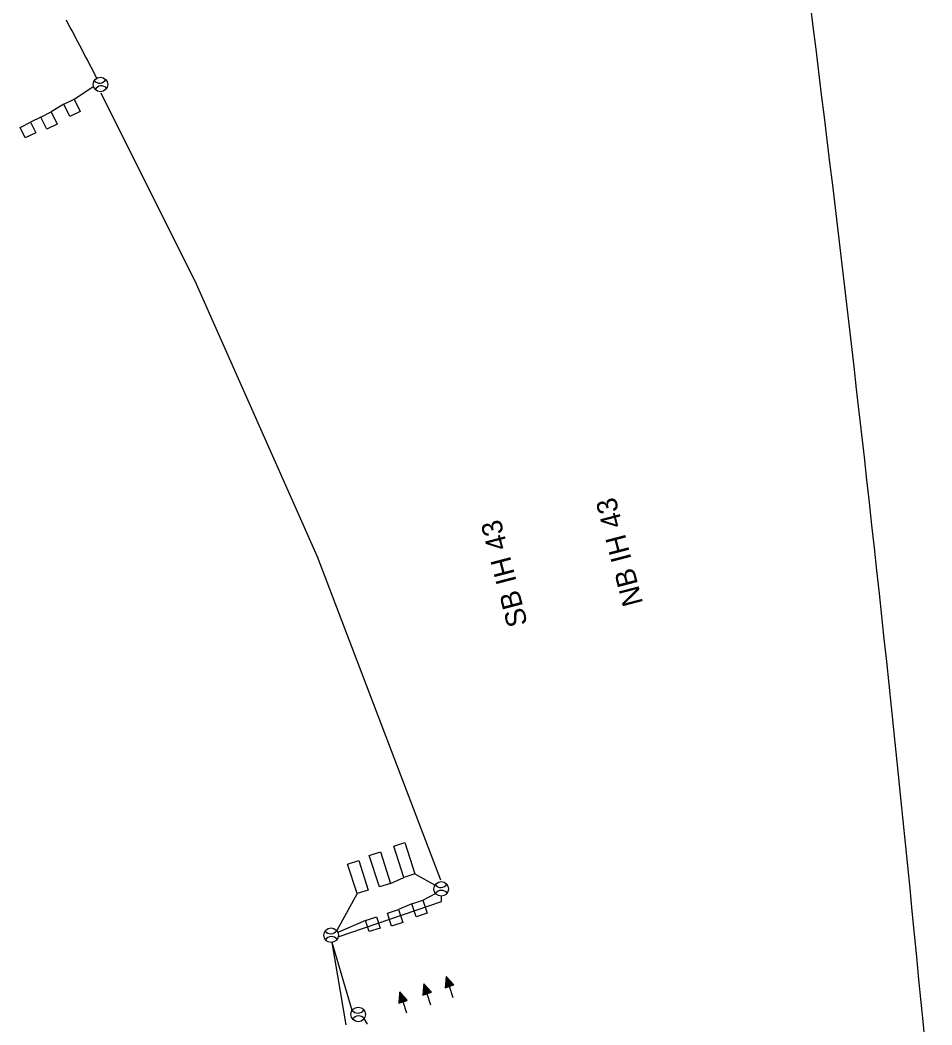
# Model space of a CAD drawing. Extents: x 601562 to 605316, y 332050 to 402250.
# Drawn here: x 603881 to 604350, y 348982 to 349499 of the extents above; entities that cross this region are included whole.
import ezdxf

# ---------------------------------------------------------------- set-up
doc = ezdxf.new("R2010")
doc.units = 0
for name, color, linetype in [('Default', 7, 'Continuous'), ('P_FTMS', 7, 'Continuous'), ('P_FTMSConduit', 7, 'Continuous')]:
    doc.layers.add(name, color=color, linetype=linetype)

# ---------------------------------------------------------------- blocks, each defined once
blk = doc.blocks.new('POINT_DISPLAY')
at = {"layer": 'Default'}
blk.add_line((0, 0), (0, 0), dxfattribs=at)
blk = doc.blocks.new('_U228')
at = {"layer": 'P_FTMS'}
for p, q in [((-4.52, 3.24), (1.52, -0.2)), ((-4.41, 2.83), (1.26, -0.4)), ((-4.34, 3.49), (1.77, 0.01)), ((-3.86, 3.43), (-4.34, 2.58)), ((-4.29, 2.41), (1, -0.61)), ((-3.53, 3.38), (-4.22, 2.16)), ((-4.18, 2), (0.75, -0.81)), ((-3.21, 3.34), (-4.11, 1.75)), ((-4.07, 1.58), (0.49, -1.01)), ((-2.88, 3.29), (-4, 1.33)), ((-3.95, 1.16), (0.23, -1.22)), ((-2.56, 3.25), (-3.88, 0.92)), ((-3.84, 0.75), (-0.02, -1.42)), ((-2.23, 3.2), (-3.77, 0.5)), ((-3.72, 0.33), (-0.28, -1.63)), ((-1.91, 3.16), (-3.66, 0.08)), ((-1.58, 3.11), (-3.54, -0.33)), ((-3.53, 3.38), (2.03, 0.21)), ((-1.25, 3.07), (-3.43, -0.75)), ((-0.93, 3.02), (-3.31, -1.16)), ((-0.6, 2.98), (-3.2, -1.58)), ((-0.28, 2.93), (-3.09, -1.99)), ((0.05, 2.89), (-2.97, -2.41)), ((0.37, 2.84), (-2.86, -2.83)), ((0.7, 2.8), (-2.74, -3.24)), ((-2.72, 3.27), (2.29, 0.42)), ((1.02, 2.75), (-2.46, -3.37)), ((-1.91, 3.16), (2.54, 0.62)), ((1.35, 2.71), (-1.82, -2.86)), ((1.67, 2.66), (-1.18, -2.34)), ((-1.09, 3.04), (2.8, 0.83)), ((2, 2.62), (-0.54, -1.83)), ((-0.28, 2.93), (3.06, 1.03)), ((2.32, 2.57), (0.1, -1.32)), ((0.53, 2.82), (3.31, 1.23)), ((2.65, 2.53), (0.75, -0.81)), ((1.35, 2.71), (3.57, 1.44)), ((2.97, 2.48), (1.39, -0.3)), ((3.3, 2.44), (2.03, 0.21)), ((2.16, 2.59), (3.83, 1.64)), ((3.62, 2.39), (2.67, 0.72)), ((2.97, 2.48), (4.08, 1.85)), ((3.95, 2.35), (3.31, 1.23)), ((3.79, 2.37), (4.34, 2.05)), ((4.27, 2.3), (3.96, 1.75)), ((-3.61, -0.08), (-0.54, -1.83)), ((-3.5, -0.5), (-0.79, -2.04)), ((-3.38, -0.91), (-1.05, -2.24)), ((-3.27, -1.33), (-1.31, -2.45)), ((-3.15, -1.75), (-1.57, -2.65)), ((-3.04, -2.16), (-1.82, -2.86)), ((-2.93, -2.58), (-2.08, -3.06)), ((-2.81, -2.99), (-2.34, -3.26)), ((-2.7, -3.41), (-2.59, -3.47))]:
    blk.add_line(p, q, dxfattribs=at)
blk.add_lwpolyline([(-4.6, 3.53), (4.6, 2.26), (-2.67, -3.53)], close=True, dxfattribs=at)
blk.add_blockref('POINT_DISPLAY', (4.6, 2.26), dxfattribs=at)
blk = doc.blocks.new('_U229')
at = {"layer": 'P_FTMS'}
for p, q in [((-4.52, 3.24), (1.52, -0.2)), ((-4.41, 2.83), (1.26, -0.4)), ((-4.34, 3.49), (1.77, 0.01)), ((-3.86, 3.43), (-4.34, 2.58)), ((-4.29, 2.41), (1, -0.61)), ((-3.53, 3.38), (-4.22, 2.16)), ((-4.18, 2), (0.75, -0.81)), ((-3.21, 3.34), (-4.11, 1.75)), ((-4.07, 1.58), (0.49, -1.01)), ((-2.88, 3.29), (-4, 1.33)), ((-3.95, 1.16), (0.23, -1.22)), ((-2.56, 3.25), (-3.88, 0.92)), ((-3.84, 0.75), (-0.02, -1.42)), ((-2.23, 3.2), (-3.77, 0.5)), ((-3.72, 0.33), (-0.28, -1.63)), ((-1.91, 3.16), (-3.66, 0.08)), ((-1.58, 3.11), (-3.54, -0.33)), ((-3.53, 3.38), (2.03, 0.21)), ((-1.25, 3.07), (-3.43, -0.75)), ((-0.93, 3.02), (-3.31, -1.16)), ((-0.6, 2.98), (-3.2, -1.58)), ((-0.28, 2.93), (-3.09, -1.99)), ((0.05, 2.89), (-2.97, -2.41)), ((0.37, 2.84), (-2.86, -2.83)), ((0.7, 2.8), (-2.74, -3.24)), ((-2.72, 3.27), (2.29, 0.42)), ((1.02, 2.75), (-2.46, -3.37)), ((-1.91, 3.16), (2.54, 0.62)), ((1.35, 2.71), (-1.82, -2.86)), ((1.67, 2.66), (-1.18, -2.34)), ((-1.09, 3.04), (2.8, 0.83)), ((2, 2.62), (-0.54, -1.83)), ((-0.28, 2.93), (3.06, 1.03)), ((2.32, 2.57), (0.1, -1.32)), ((0.53, 2.82), (3.31, 1.23)), ((2.65, 2.53), (0.75, -0.81)), ((1.35, 2.71), (3.57, 1.44)), ((2.97, 2.48), (1.39, -0.3)), ((3.3, 2.44), (2.03, 0.21)), ((2.16, 2.59), (3.83, 1.64)), ((3.62, 2.39), (2.67, 0.72)), ((2.97, 2.48), (4.08, 1.85)), ((3.95, 2.35), (3.31, 1.23)), ((3.79, 2.37), (4.34, 2.05)), ((4.27, 2.3), (3.96, 1.75)), ((-3.61, -0.08), (-0.54, -1.83)), ((-3.5, -0.5), (-0.79, -2.04)), ((-3.38, -0.91), (-1.05, -2.24)), ((-3.27, -1.33), (-1.31, -2.45)), ((-3.15, -1.75), (-1.57, -2.65)), ((-3.04, -2.16), (-1.82, -2.86)), ((-2.93, -2.58), (-2.08, -3.06)), ((-2.81, -2.99), (-2.34, -3.26)), ((-2.7, -3.41), (-2.59, -3.47))]:
    blk.add_line(p, q, dxfattribs=at)
blk.add_lwpolyline([(-4.6, 3.53), (4.6, 2.26), (-2.67, -3.53)], close=True, dxfattribs=at)
blk.add_blockref('POINT_DISPLAY', (4.6, 2.26), dxfattribs=at)

msp = doc.modelspace()

# ---------------------------------------------------------------- linework, layer by layer
at = {"layer": 'P_FTMS'}
for p, q in [((603908.52, 349458.66), (603918.12, 349464.93)), ((603903.13, 349456.03), (603896.74, 349452.1)), ((603891.35, 349449.46), (603886.07, 349446.78)), ((604071.41, 349055.02), (604078.29, 349058.01)), ((604083.99, 349059.86), (604094.33, 349054.17)), ((604054.23, 349049.74), (604043.68, 349030.73)), ((604088.1, 349046.33), (604094.62, 349049.78)), ((604082.39, 349044.48), (604075.51, 349041.49)), ((604058.49, 349035.87), (604044.23, 349029.81)), ((604103.73, 348996.15), (604101.76, 349002)), ((604092.19, 348992.37), (604090.23, 348998.22)), ((604079.81, 348988.18), (604077.85, 348994.03))]:
    msp.add_line(p, q, dxfattribs=at)
for points in [[(603906.21, 349449.74), (603903.13, 349456.03), (603903.13, 349456.03), (603908.52, 349458.66), (603911.59, 349452.38), (603906.21, 349449.74)], [(603894.43, 349443.17), (603891.35, 349449.46), (603891.35, 349449.46), (603896.74, 349452.1), (603899.81, 349445.81), (603894.43, 349443.17)], [(603880.67, 349444.15), (603886.07, 349446.78), (603888.7, 349441.39), (603883.31, 349438.76), (603880.67, 349444.15)], [(604073.04, 349074.18), (604078.74, 349076.03), (604083.99, 349059.86), (604078.29, 349058.01), (604078.29, 349058.01), (604073.04, 349074.18)], [(604049.29, 349064.96), (604055, 349066.81), (604059.94, 349051.59), (604054.23, 349049.74), (604049.29, 349064.96)], [(604060.45, 349069.34), (604066.16, 349071.19), (604071.41, 349055.02), (604065.7, 349053.17), (604065.7, 349053.16), (604060.45, 349069.34)], [(604084.56, 349037.82), (604082.39, 349044.48), (604082.39, 349044.48), (604088.1, 349046.33), (604090.26, 349039.68), (604084.56, 349037.82)], [(604071.97, 349032.98), (604069.81, 349039.64), (604069.81, 349039.64), (604075.51, 349041.49), (604077.67, 349034.83), (604071.97, 349032.98)], [(604058.49, 349035.87), (604064.2, 349037.73), (604066.05, 349032.02), (604060.34, 349030.17), (604058.49, 349035.87)]]:
    msp.add_lwpolyline(points, dxfattribs=at)
for centre in [(603922.06, 349466.22), (604097.52, 349052.16), (604040.78, 349028.35), (604054.77, 348987.54)]:
    msp.add_circle(centre, 3.75, dxfattribs=at)
for centre, start, end in [((603921.62, 349470.7), 222.4831, 328.7387), ((603922.5, 349461.74), 42.4831, 148.7387), ((604097.32, 349056.66), 219.4323, 325.6879), ((604097.72, 349047.67), 39.4323, 145.6879), ((604040.58, 349032.84), 219.4323, 325.6879), ((604040.98, 349023.85), 39.4323, 145.6879), ((604054.57, 348992.04), 219.4323, 325.6879), ((604054.98, 348983.05), 39.4323, 145.6879)]:
    msp.add_arc(centre, 3.75, start, end, dxfattribs=at)
at = {"layer": 'P_FTMSConduit'}
for p, q in [((603971.54, 349363.49), (603922.5, 349461.74)), ((604033.74, 349223.09), (603971.54, 349363.49)), ((604097.32, 349056.66), (604033.74, 349223.09)), ((604044.44, 349027.52), (604097.67, 349045.76)), ((604097.67, 349045.76), (604097.61, 349048.41)), ((604048.55, 348982.18), (604041.4, 349024.65)), ((604051.68, 348989.66), (604041.4, 349024.65)), ((604059.51, 348982.49), (604057.87, 348985.43))]:
    msp.add_line(p, q, dxfattribs=at)
for centre, radius, start, end in [((586818.85, 347308.18), 17606.64, 5.302764, 7.750421), ((600886.71, 347893.57), 3418.42, 27.45203, 28.01789), ((604100.14, 349057.81), 0.001, 349.2519, 16.8351)]:
    msp.add_arc(centre, radius, start, end, dxfattribs=at)

# ---------------------------------------------------------------- block references
at = {"layer": 'P_FTMS', "xscale": 0.6330710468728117, "yscale": -0.6330710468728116, "rotation": 123.87368883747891}
for name, p in [('_U228', (604100.48, 349003.9)), ('_U229', (604076.56, 348995.93)), ('_U228', (604088.94, 349000.13))]:
    msp.add_blockref(name, p, dxfattribs=at)

# ---------------------------------------------------------------- texts
at = {"layer": 'P_FTMSConduit'}
for s, p in [('NB IH 43', (604201.46, 349199.22)), ('SB IH 43', (604142.07, 349188.54))]:
    msp.add_text(s, height=10.5, rotation=104.6085, dxfattribs=at).set_placement(p)

doc.saveas('drawing.dxf')
